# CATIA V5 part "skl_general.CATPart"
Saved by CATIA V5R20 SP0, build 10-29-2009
Part number: skl_general
Publications: "Longueur_1", "Longueur_2", "Longueur_3", "Longueur_4", "Point.A", "Point.L", "Point.N", "Point.G", "Point.C", "Point.K", "Point.E", "Point.H", "Point.D", "Point.F", "Point.B", "Plan_Ref"
Bounding box of the stored display mesh (mm): x -159.748 to 394.671, y -440 to 313.648, z 0 to 0
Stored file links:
  C:\Users\Matthieu\Desktop\IFMA\Cours 2A\Thinkmotion\skl_general.CATPart
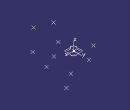
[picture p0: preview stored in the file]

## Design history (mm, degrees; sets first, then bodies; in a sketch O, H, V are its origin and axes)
Parameters
  Longueur_1 = 420 mm
  Longueur_2 = 170 mm
  Longueur_3 = 300 mm
  Longueur_4 = 440 mm
AxisSystem1: origin (0, 0, 0), X (1, 0, 0), Y (0, 1, 0), Z (0, 0, 1)
Body1 (main body)
  Plane1 "Plan_Ref": type Offset, RefPlane xy-plane, Offset 0
  Point1 "Point.A": (0, 0, 0), in AxisSystem1
  Point2 "Point.L": (0, 170 {= Longueur_2}, 0), relative to Point1, in AxisSystem1
  Point3 "Point.N": (0, -170 {= -Longueur_2}, 0), relative to Point1, in AxisSystem1
  Point4 "Point.G": (300 {= Longueur_3}, 0, 0), relative to Point1, in AxisSystem1
  Point5 "Point.C": (-159.7477 {= -Longueur_2 *cos(20deg)}, 58.1434 {= Longueur_2 *sin(20deg)}, 0), in AxisSystem1
  Point6 "Point.K": (159.7477 {= Longueur_2 *cos(20deg)}, -58.1434 {= -sin(20deg)*Longueur_2}, 0), in AxisSystem1
  Point7 "Point.E": (394.6709 {= Longueur_1 *cos(20deg)}, 143.6485 {= Longueur_1 *sin(20deg)}, 0), relative to Point5, in AxisSystem1
  Point8 "Point.H": (394.6709 {= Longueur_1 *cos(20deg)}, 143.6485 {= Longueur_1 *sin(20deg)}, 0), relative to Point2, in AxisSystem1
  Point9 "Point.D": (0, -440 {= -Longueur_4}, 0), relative to Point5, in AxisSystem1
  Point10 "Point.F": (0, -420 {= -Longueur_1}, 0), relative to Point7, in AxisSystem1
  Point11 "Point.B": (159.7477 {= Longueur_2 *cos(20deg)}, -58.1434 {= -Longueur_2 *sin(20deg)}, 0), relative to Point9, in AxisSystem1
